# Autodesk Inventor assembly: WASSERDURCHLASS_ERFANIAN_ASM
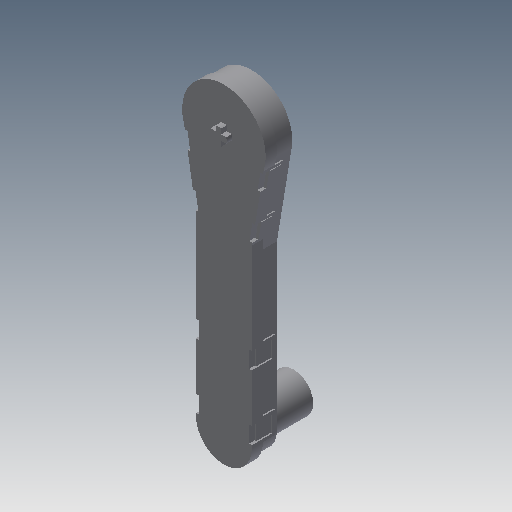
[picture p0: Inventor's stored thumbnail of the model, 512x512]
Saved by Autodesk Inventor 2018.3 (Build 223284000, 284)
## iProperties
Created: 2019-01
Part Number: WASSERDURCHLASS_ERFANIAN_ASM
Material: Generisch
Document SubType Name: Assembly
Designer: zand
Author: zand
Revision Number: 7LAST_VERSION
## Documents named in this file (3)
- D:\10_CAD-ÜBUNGEN\KAFFEEMASCHINE\Workspaces\Arbeitsbereich\WASSERDURCHLASS_ERFANIAN_ASM.iam
- D:\10_CAD-ÜBUNGEN\KAFFEEMASCHINE\Workspaces\Arbeitsbereich\WASSERDURCHLASS_ERFANIAN.ipt
- D:\10_CAD-ÜBUNGEN\KAFFEEMASCHINE\Workspaces\Arbeitsbereich\WASSERDURCHLAS_UNTER_ERFANIAN.ipt
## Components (2 placed, 2 different names)
1. Wasserdurchlass
2. Wasserdurchlass_unten
